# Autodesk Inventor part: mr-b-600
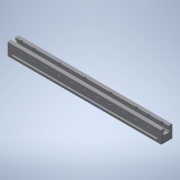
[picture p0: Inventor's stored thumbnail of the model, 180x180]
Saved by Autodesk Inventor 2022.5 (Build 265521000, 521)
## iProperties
Created: 2016-12
Part Number: mr-b-600
Material: 一般
Document SubType Name: Modeling
Designer: imaocorp
Density: 1 g/cm^3
Appearance: 既定
Author: imaocorp
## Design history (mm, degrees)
node "mr-b-600.x_t1"
node "mr-b-600"
node "Base1"
